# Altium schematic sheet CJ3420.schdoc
size 127 x 101 mm
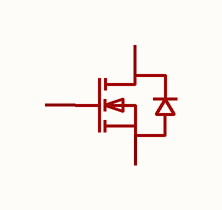
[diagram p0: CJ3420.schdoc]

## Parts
Q?  cj3420  [SOT-23_L2.9-W1.3-P1.90-LS2.4-BR]  (value not drawn)

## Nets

Not connected (* = marked no-connect by the designer): Q? 1(G) 2(S) 3(D)

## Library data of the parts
Q? = cj3420: 数量:1个N沟道;漏源电压(Vdss):20V;连续漏极电流(Id):6A;导通电阻(RDS(on)):24mΩ@10V;耗散功率(Pd):350mW;阈值电压(Vgs(th)):500mV;; Manufacturer: CJ(江苏长电/长晶); AddInBom: yes; ModelId: c62791f0466c4ae2a892c056b845b0ca; ModelName: SOT-23-3P_L2.9-W1.3-H1.0-LS2.4-P0.95; ModelTransform: 98.64468,114.173,0,180,0,0,0.001,-0.002,0; Number: 1个N沟道; Drain to Source Voltage: 20V; Current - Continuous Drain(Id): 6A; Pd - Power Dissipation: 350mW; Gate Threshold Voltage (Vgs(th)): 500mV; Input Capacitance(Ciss): 630pF; Reverse Transfer Capacitance (Crss@Vds): 137pF; Type: N沟道; Output Capacitance(Coss): 164pF; Vgs: ±12V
